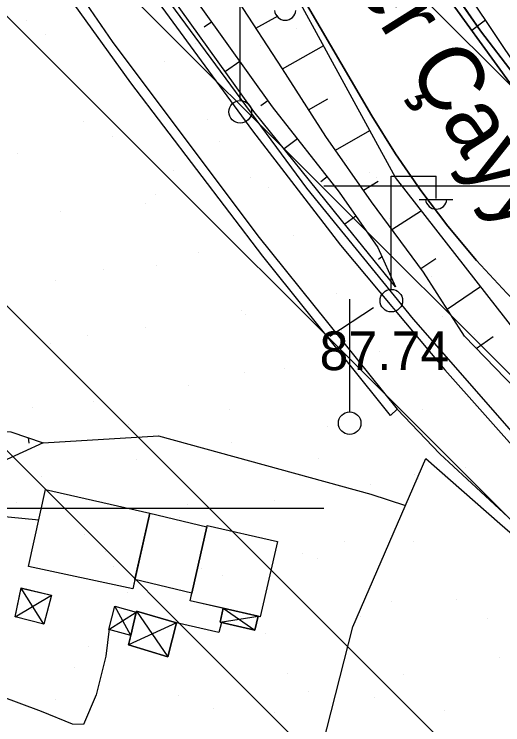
# Model space of a CAD drawing. Extents: x 417995 to 421451, y 4454518 to 4458015.
# Drawn here: x 421134.4 to 421210.1, y 4456673.3 to 4456783.5 of the extents above; entities that cross this region are included whole.
import ezdxf

# ---------------------------------------------------------------- set-up
doc = ezdxf.new("R2010")
doc.units = 0
for name, color, linetype in [('ADAKENARI', 7, 'Continuous'), ('B_Mesken', 7, 'Continuous'), ('B_Sundurma', 7, 'Continuous'), ('Default', 7, 'Continuous'), ('Hid_Dere_Sulu_Yat_Gen', 7, 'Continuous'), ('PL_AYA_BOLGE_PARKI', 7, 'Continuous'), ('PL_KA_TARIM_ALANI', 7, 'Continuous'), ('PL_TA_K_DERE', 7, 'Continuous'), ('S_Elektrik_Diregi', 7, 'Continuous'), ('S_Telefon_Diregi', 7, 'Continuous'), ('Sev_Sevalti', 7, 'Continuous'), ('Sev_Sevustu', 7, 'Continuous'), ('Sev_Tarama', 7, 'Continuous'), ('Sinir_itirazli_Mulkiyet', 7, 'Continuous'), ('Sinir_Tel_bir_taraf', 7, 'Continuous'), ('SN_TR_SIVILASMA', 7, 'Continuous'), ('SN_TR_TASKIN', 7, 'Continuous'), ('TR_PARKALANI', 7, 'Continuous'), ('Y_Cay_Dere', 7, 'Continuous'), ('Y_Yol_Kotu', 7, 'Continuous'), ('Yol_Kaldirim_kenari_bordurtasi', 7, 'Continuous'), ('Yol_Sose', 7, 'Continuous')]:
    doc.layers.add(name, color=color, linetype=linetype)

# ---------------------------------------------------------------- blocks, each defined once
blk = doc.blocks.new('POINT_DISPLAY')
at = {"layer": 'Default'}
blk.add_line((0, 0), (0, 0), dxfattribs=at)

msp = doc.modelspace()

# ---------------------------------------------------------------- linework, layer by layer
at = {"layer": 'ADAKENARI'}
for p, q in [((421189.87, 4456767.74), (421160.65, 4456817.75)), ((421201.78, 4456788.03), (421206.67, 4456780.95)), ((421206.67, 4456780.95), (421211.91, 4456774.13)), ((421193.51, 4456761.85), (421189.87, 4456767.74)), ((421197.42, 4456756.15), (421193.51, 4456761.85)), ((421201.61, 4456750.64), (421197.42, 4456756.15)), ((421206.06, 4456745.34), (421201.61, 4456750.64)), ((421210.76, 4456740.27), (421206.06, 4456745.34))]:
    msp.add_line(p, q, dxfattribs=at)
at = {"layer": 'B_Mesken'}
for points in [[(421155.42, 4456706.15), (421152.81, 4456694.39), (421136.64, 4456697.9), (421139.27, 4456709.8)], [(421155.42, 4456706.15), (421153.14, 4456695.88), (421152.81, 4456694.39), (421136.64, 4456697.9), (421139.27, 4456709.8)], [(421155.42, 4456706.15), (421164.27, 4456704.03), (421161.97, 4456693.73), (421153.14, 4456695.88)], [(421155.42, 4456706.15), (421164.27, 4456704.03), (421161.97, 4456693.73), (421153.14, 4456695.88)], [(421175.21, 4456701.74), (421172.53, 4456690.09), (421161.71, 4456692.56), (421164.32, 4456704.23)], [(421175.21, 4456701.74), (421172.53, 4456690.09), (421172.21, 4456690.16), (421166.82, 4456691.4), (421161.71, 4456692.56), (421161.97, 4456693.73), (421164.27, 4456704.03), (421164.32, 4456704.23)]]:
    msp.add_lwpolyline(points, close=True, dxfattribs=at)
at = {"layer": 'B_Sundurma'}
for p, q in [((421139.02, 4456688.94), (421135.53, 4456694.54)), ((421134.55, 4456690.08), (421140.23, 4456693.42)), ((421149.1, 4456688.12), (421153.32, 4456690.81)), ((421152.48, 4456687.19), (421150.01, 4456691.75)), ((421153.36, 4456690.97), (421158.25, 4456683.88)), ((421166.82, 4456691.4), (421171.73, 4456687.99)), ((421166.32, 4456689.23), (421172.21, 4456690.16)), ((421159.56, 4456689.13), (421152.14, 4456685.75))]:
    msp.add_line(p, q, dxfattribs=at)
for points in [[(421139.02, 4456688.94), (421134.55, 4456690.08), (421135.53, 4456694.55), (421140.23, 4456693.42)], [(421139.02, 4456688.94), (421134.55, 4456690.08), (421135.53, 4456694.54), (421140.23, 4456693.42)], [(421152.48, 4456687.19), (421149.1, 4456688.12), (421150.01, 4456691.75), (421153.32, 4456690.81)], [(421152.48, 4456687.19), (421149.1, 4456688.12), (421150.01, 4456691.75), (421153.32, 4456690.81)], [(421159.56, 4456689.13), (421153.36, 4456690.97), (421152.14, 4456685.75), (421158.25, 4456683.88)], [(421159.56, 4456689.13), (421158.25, 4456683.88), (421152.14, 4456685.75), (421152.48, 4456687.19), (421153.32, 4456690.81), (421153.36, 4456690.97)], [(421166.82, 4456691.4), (421166.32, 4456689.23), (421171.73, 4456687.99), (421172.21, 4456690.16)], [(421166.82, 4456691.4), (421172.21, 4456690.16), (421171.73, 4456687.99), (421166.32, 4456689.23)]]:
    msp.add_lwpolyline(points, close=True, dxfattribs=at)
at = {"layer": 'Hid_Dere_Sulu_Yat_Gen'}
for points in [[(421284.27, 4456711.67), (421270.13, 4456721.8), (421262.99, 4456725.89), (421247.78, 4456741.35), (421234.53, 4456752.13), (421224.93, 4456758.84), (421223.96, 4456759.08), (421223.19, 4456759.17), (421222.1, 4456760.09), (421211.16, 4456772.91), (421200.4, 4456787.84), (421194, 4456797.29), (421184.08, 4456815.05)], [(421284, 4456685.74), (421276.33, 4456692.49), (421245.28, 4456712.53), (421224.54, 4456721.77), (421212.26, 4456734.15), (421193.52, 4456758.21), (421167.24, 4456806.43)]]:
    msp.add_lwpolyline(points, dxfattribs=at)
at = {"layer": 'PL_AYA_BOLGE_PARKI'}
msp.add_lwpolyline([(421283.96, 4456682.26), (421226.26, 4456726.49), (421220.87, 4456730.83), (421215.7, 4456735.43), (421210.76, 4456740.27), (421206.06, 4456745.34), (421201.61, 4456750.64), (421197.42, 4456756.15), (421193.51, 4456761.85), (421189.87, 4456767.74), (421160.65, 4456817.75), (421151.42, 4456836.67), (421082.65, 4456883.98), (421111.56, 4456846.79), (421087.01, 4456805.84), (420984.38, 4456839.22), (420959.97, 4456579.21), (420809.99, 4456617.84)], dxfattribs=at)
at = {"layer": 'PL_KA_TARIM_ALANI'}
msp.add_lwpolyline([(421285.24, 4456804.82), (421181.25, 4456847.12), (421179.74, 4456847.51), (421178.18, 4456847.48), (421176.68, 4456847.03), (421175.36, 4456846.19), (421174.31, 4456845.04), (421173.61, 4456843.64), (421173.31, 4456842.11), (421173.43, 4456840.55), (421173.96, 4456839.08), (421193.04, 4456802.84), (421197.23, 4456795.33), (421201.78, 4456788.03), (421206.67, 4456780.95), (421211.91, 4456774.13), (421217.47, 4456767.56), (421223.34, 4456761.28), (421229.51, 4456755.28), (421235.96, 4456749.6), (421242.69, 4456744.23), (421284.28, 4456712.63)], dxfattribs=at)
at = {"layer": 'PL_TA_K_DERE'}
for points in [[(421284.28, 4456712.63), (421242.69, 4456744.23), (421235.96, 4456749.6), (421229.51, 4456755.28), (421223.34, 4456761.28), (421217.47, 4456767.56), (421211.91, 4456774.13), (421206.67, 4456780.95), (421201.78, 4456788.03), (421197.23, 4456795.33), (421193.04, 4456802.84), (421173.96, 4456839.08), (421173.43, 4456840.55), (421173.31, 4456842.11), (421173.61, 4456843.64), (421174.31, 4456845.04), (421175.36, 4456846.19), (421176.68, 4456847.03), (421178.18, 4456847.48), (421179.74, 4456847.51), (421181.25, 4456847.12), (421285.24, 4456804.82)], [(421160.65, 4456817.75), (421189.87, 4456767.74), (421193.51, 4456761.85), (421197.42, 4456756.15), (421201.61, 4456750.64), (421206.06, 4456745.34), (421210.76, 4456740.27), (421215.7, 4456735.43), (421220.87, 4456730.83), (421226.26, 4456726.49), (421283.96, 4456682.26)]]:
    msp.add_lwpolyline(points, dxfattribs=at)
at = {"layer": 'S_Elektrik_Diregi'}
for p, q in [((421169.43, 4456770.21), (421169.43, 4456787.71)), ((421192.83, 4456740.92), (421192.83, 4456758.42)), ((421192.83, 4456758.42), (421199.83, 4456758.42)), ((421199.83, 4456754.92), (421199.83, 4456758.42)), ((421197.17, 4456754.78), (421202.42, 4456754.78))]:
    msp.add_line(p, q, dxfattribs=at)
for centre in [(421169.46, 4456768.38), (421192.87, 4456739.09)]:
    msp.add_circle(centre, 1.75, dxfattribs=at)
for centre in [(421176.43, 4456784.23), (421199.83, 4456754.94)]:
    msp.add_arc(centre, 1.66, 184.8384, 355.1464, dxfattribs=at)
at = {"layer": 'S_Telefon_Diregi'}
for p, q in [((421186.45, 4456721.85), (421186.45, 4456739.35)), ((421183.33, 4456733.58), (421190.09, 4456738.02))]:
    msp.add_line(p, q, dxfattribs=at)
msp.add_circle((421186.41, 4456720.1), 1.75, dxfattribs=at)
at = {"layer": 'Sev_Sevalti'}
for points in [[(421284, 4456685.74), (421276.33, 4456692.49), (421245.28, 4456712.53), (421224.54, 4456721.77), (421212.26, 4456734.15), (421193.52, 4456758.21), (421167.24, 4456806.43), (421151.75, 4456837.84), (421141.09, 4456853.41), (421105.91, 4456887.43), (421070.85, 4456910.57)], [(421193.49, 4456741.23), (421185.16, 4456751.59), (421171.56, 4456768.44), (421156.17, 4456789.91), (421144.72, 4456806.59), (421135.11, 4456822.89), (421127.71, 4456833.97), (421117.33, 4456847.01), (421101.39, 4456865.31), (421087.45, 4456880.68), (421085.21, 4456884.49)], [(421285.29, 4456809.93), (421272.07, 4456815.33), (421247.22, 4456826.37), (421216.18, 4456839.09), (421184.98, 4456853.08), (421178.14, 4456854.82), (421165.07, 4456855.44), (421171.01, 4456841.15), (421184.08, 4456815.05), (421194, 4456797.29), (421200.4, 4456787.84), (421211.16, 4456772.91), (421222.1, 4456760.09), (421223.19, 4456759.17), (421223.96, 4456759.08), (421224.93, 4456758.84), (421234.53, 4456752.13), (421247.78, 4456741.35), (421262.99, 4456725.89), (421270.13, 4456721.8), (421284.27, 4456711.67)], [(421138.91, 4456717.05), (421132.63, 4456714.18)]]:
    msp.add_lwpolyline(points, dxfattribs=at)
at = {"layer": 'Sev_Sevustu'}
for points in [[(421085.21, 4456884.49), (421091.11, 4456879.45), (421099.7, 4456870.6), (421110.8, 4456858.46), (421123.65, 4456843.28), (421133.23, 4456830.07), (421142.43, 4456815.35), (421152.91, 4456799.03), (421163.63, 4456784.22), (421174.4, 4456769.14), (421184.79, 4456755.92), (421190.78, 4456747.31), (421193.49, 4456741.23)], [(421180.06, 4456830.58), (421186.89, 4456815.36), (421195.62, 4456800.61), (421205.15, 4456786.05), (421212.6, 4456774.88), (421222.25, 4456763.68), (421224.33, 4456761.82), (421226.37, 4456762.4)], [(421283.8, 4456666.93), (421274.06, 4456674.35), (421264.43, 4456681.85), (421256.83, 4456688.79), (421244.81, 4456698.34), (421237.3, 4456705.03), (421231.54, 4456708.49), (421230.73, 4456709.12), (421226.67, 4456713.62), (421222.69, 4456716.73), (421213.71, 4456723.75), (421204.19, 4456733.59), (421197.86, 4456743.49), (421189.82, 4456754.41), (421182.71, 4456764.54), (421175.98, 4456775.03), (421169.15, 4456785.56)], [(420983.62, 4456725.89), (420989.23, 4456726.66), (420996.28, 4456726.36), (421011.58, 4456724.6), (421031.39, 4456723.09), (421047.4, 4456720.27), (421060.51, 4456717.63), (421074.37, 4456716), (421076.66, 4456715.93), (421077.62, 4456715.92), (421078.81, 4456716.02), (421079.89, 4456716.41), (421081.81, 4456717.14), (421083.08, 4456717.67), (421091.28, 4456720.33), (421092.48, 4456720.5), (421093.73, 4456720.61), (421114.45, 4456717.86), (421123.08, 4456717.24), (421127.32, 4456717.72), (421131.53, 4456718.83), (421133.9, 4456718.78), (421138.91, 4456717.05)]]:
    msp.add_lwpolyline(points, dxfattribs=at)
at = {"layer": 'Sev_Tarama'}
for p, q in [((421171.89, 4456781.33), (421175.35, 4456783.27)), ((421165.01, 4456782.29), (421163.89, 4456781.5)), ((421207.48, 4456782.56), (421205.36, 4456780.96)), ((421175.99, 4456775.02), (421182.39, 4456778.63)), ((421169.37, 4456776.19), (421167.15, 4456774.6)), ((421173.72, 4456770.1), (421172.63, 4456769.29)), ((421180.04, 4456768.7), (421183.01, 4456770.38)), ((421184.2, 4456762.42), (421189.55, 4456765.48)), ((421178.31, 4456764.17), (421176.25, 4456762.63)), ((421182.94, 4456758.27), (421181.95, 4456757.53)), ((421188.54, 4456756.23), (421190.82, 4456757.61)), ((421192.97, 4456750.14), (421197.54, 4456753.05)), ((421187.37, 4456752.21), (421185.67, 4456750.95)), ((421191.41, 4456745.89), (421190.88, 4456745.5)), ((421197.43, 4456744.08), (421199.78, 4456745.62)), ((421201.52, 4456737.77), (421206.71, 4456741.27)), ((421206.02, 4456731.7), (421208.64, 4456733.56)), ((421136.57, 4456717.86), (421136.7, 4456716.98))]:
    msp.add_line(p, q, dxfattribs=at)
at = {"layer": 'Sinir_itirazli_Mulkiyet'}
for points in [[(421138.91, 4456717.05), (421156.78, 4456718.11), (421189.67, 4456709.11)], [(421189.67, 4456709.11), (421195.06, 4456707.35)]]:
    msp.add_lwpolyline(points, dxfattribs=at)
at = {"layer": 'Sinir_Tel_bir_taraf'}
for points in [[(421169.45, 4456619.98), (421186.92, 4456688.51), (421198.19, 4456714.61), (421209.68, 4456704.53), (421220.87, 4456694.83)], [(421149.12, 4456688.2), (421148.63, 4456683.98), (421147.11, 4456677.97), (421145.18, 4456673.4), (421143.44, 4456673.43), (421138.64, 4456675.38), (421132.1, 4456677.82), (421131.31, 4456683.63), (421123.01, 4456687.71), (421127.08, 4456706.21), (421138.23, 4456705.09)], [(421166.56, 4456689.18), (421166.16, 4456687.62), (421159.56, 4456689.13)]]:
    msp.add_lwpolyline(points, dxfattribs=at)
at = {"layer": 'SN_TR_SIVILASMA'}
for p, q in [((421284.14, 4456699.66), (420198.29, 4457785.51)), ((421283.68, 4456655.22), (420178.33, 4457760.57)), ((421283.45, 4456633), (420168.35, 4457748.09)), ((421282.98, 4456588.57), (420148.4, 4457723.15)), ((421282.75, 4456566.35), (420138.42, 4457710.68))]:
    msp.add_line(p, q, dxfattribs=at)
at = {"layer": 'SN_TR_TASKIN'}
for p, q in [((421182.43, 4456756.9), (421282.43, 4456756.9)), ((421082.43, 4456706.9), (421182.43, 4456706.9))]:
    msp.add_line(p, q, dxfattribs=at)
at = {"layer": 'Yol_Kaldirim_kenari_bordurtasi'}
for points in [[(421214.08, 4456715.93), (421196.28, 4456736.24), (421179.8, 4456756.51), (421157.82, 4456786.38), (421142.71, 4456808.53)], [(421193.78, 4456722.28), (421192.72, 4456721.28), (421172.97, 4456745.98), (421152.51, 4456772.88), (421137.75, 4456793.46), (421128.91, 4456806.09), (421130.4, 4456807.18)]]:
    msp.add_lwpolyline(points, dxfattribs=at)
at = {"layer": 'Yol_Sose'}
for points in [[(421115.61, 4456829.87), (421128.08, 4456810.62), (421131.35, 4456805.77), (421149.6, 4456779.25), (421172.19, 4456749.14), (421193.78, 4456722.28)], [(421141.94, 4456806.97), (421150.5, 4456793.97), (421171.38, 4456765.4), (421185.01, 4456747.72), (421201.15, 4456728.37), (421213.27, 4456714.8)], [(421193.78, 4456722.28), (421200.38, 4456715.33), (421213.07, 4456703.58), (421221.49, 4456695.5), (421241.24, 4456677.21), (421262.9, 4456657.56), (421271.78, 4456647.74), (421273.91, 4456645.21), (421275.39, 4456642.98), (421277.15, 4456639.1), (421277.79, 4456636.65), (421278.02, 4456635.06), (421277.16, 4456624.68), (421274.5, 4456607.74), (421269.84, 4456579.98), (421265.16, 4456549.49), (421261.72, 4456530.4), (421259.63, 4456516.82)]]:
    msp.add_lwpolyline(points, dxfattribs=at)

# ---------------------------------------------------------------- block references
at = {"layer": 'TR_PARKALANI', "xscale": 0.1, "yscale": 0.10000000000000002}
for p in [(421136.32, 4456782.49), (421147.74, 4456781.59), (421178.15, 4456781.31), (421139.24, 4456780.4), (421162.51, 4456778.99), (421172.53, 4456778.72), (421157.75, 4456776.12), (421142.98, 4456773.51), (421179.19, 4456769.74), (421145.13, 4456766.82), (421164.41, 4456767.14), (421149.64, 4456764.53), (421166.19, 4456763.84), (421134.87, 4456761.93), (421185.85, 4456760.76), (421159.04, 4456759.29), (421189.45, 4456759.01), (421171.08, 4456758.16), (421190.53, 4456758.16), (421173.81, 4456756.69), (421156.3, 4456755.55), (421154.7, 4456754.2), (421141.53, 4456752.95), (421192.51, 4456751.78), (421177.74, 4456749.18), (421162.96, 4456746.58), (421148.19, 4456743.97), (421156.43, 4456744.52), (421199.17, 4456742.8), (421140.79, 4456742.2), (421184.4, 4456740.2), (421169.62, 4456737.6), (421170.34, 4456736.99), (421181.64, 4456737.65), (421200.75, 4456736.7), (421154.85, 4456734.99), (421145.8, 4456733.68), (421185.11, 4456734.39), (421205.83, 4456733.82), (421140.08, 4456732.39), (421205.99, 4456731.97), (421191.06, 4456731.22), (421176.28, 4456728.62), (421170.15, 4456728.01), (421161.51, 4456726.01), (421146.74, 4456723.41), (421137.32, 4456722.5), (421167.73, 4456722.22), (421197.72, 4456722.24), (421152.09, 4456719.9), (421182.95, 4456719.64), (421168.17, 4456717.03), (421153.4, 4456714.43), (421181.64, 4456714.69), (421204.38, 4456713.26), (421138.63, 4456711.82), (421196.41, 4456712.08), (421189.61, 4456710.66), (421197.09, 4456711.45), (421134.72, 4456707.73), (421161.26, 4456707.49), (421174.83, 4456708.05), (421160.06, 4456705.45), (421145.29, 4456702.84), (421185.6, 4456701.81), (421196.27, 4456701.68), (421148.62, 4456700.2), (421179.03, 4456699.92), (421181.49, 4456699.07), (421149.77, 4456697.85), (421163.39, 4456697.6), (421166.72, 4456696.47), (421151.95, 4456693.86), (421192.94, 4456692.39), (421202.93, 4456692.7), (421137.18, 4456691.26), (421188.15, 4456690.09), (421207.71, 4456689.78), (421173.38, 4456687.49), (421146.01, 4456685.43), (421158.61, 4456684.88), (421209.59, 4456683.72), (421143.84, 4456682.28), (421176.71, 4456681.29), (421194.82, 4456681.11), (421159.92, 4456677.9), (421180.04, 4456678.51), (421190.33, 4456677.62), (421140.87, 4456677.33), (421165.27, 4456675.9), (421174.69, 4456675.3), (421201.06, 4456675.62)]:
    msp.add_blockref('POINT_DISPLAY', p, dxfattribs=at)

# ---------------------------------------------------------------- texts
at = {"layer": 'Y_Cay_Dere'}
msp.add_text('Nilüfer Çayý', height=10, rotation=302.2143, dxfattribs=at).set_placement((421172.65, 4456811.03))
at = {"layer": 'Y_Yol_Kotu'}
msp.add_text('87.74', height=6, dxfattribs=at).set_placement((421181.75, 4456728.32))

doc.saveas('drawing.dxf')
